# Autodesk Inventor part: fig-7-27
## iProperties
Shininess: 77.0
Length Units: 11269
Angle Units: 11279
Time Units: 11290
Mass Units: 11283
Length Display Precision: 3
Angle Display Precision: 2
Created: 2002-01
Part Number: fig-7-27
Document SubType Name: Modeling
Designer: CADSoft
Density: 1 g/cm^3
Density: 0.0
Volumn: 0.0
Area: 0.0
PropertySet Name: Model Information
Control State: 0
Master: False
Checked Out: False
Author: CADSoft
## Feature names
1. Coil5
